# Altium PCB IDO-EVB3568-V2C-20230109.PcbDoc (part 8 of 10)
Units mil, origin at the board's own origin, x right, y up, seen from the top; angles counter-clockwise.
Board outline 5318 x 3544 mil, 2 copper layers (TOP, BOTTOM), stack 6.8 mil thick; 790 components, 626 nets, 2890 pads, 1922 vias.
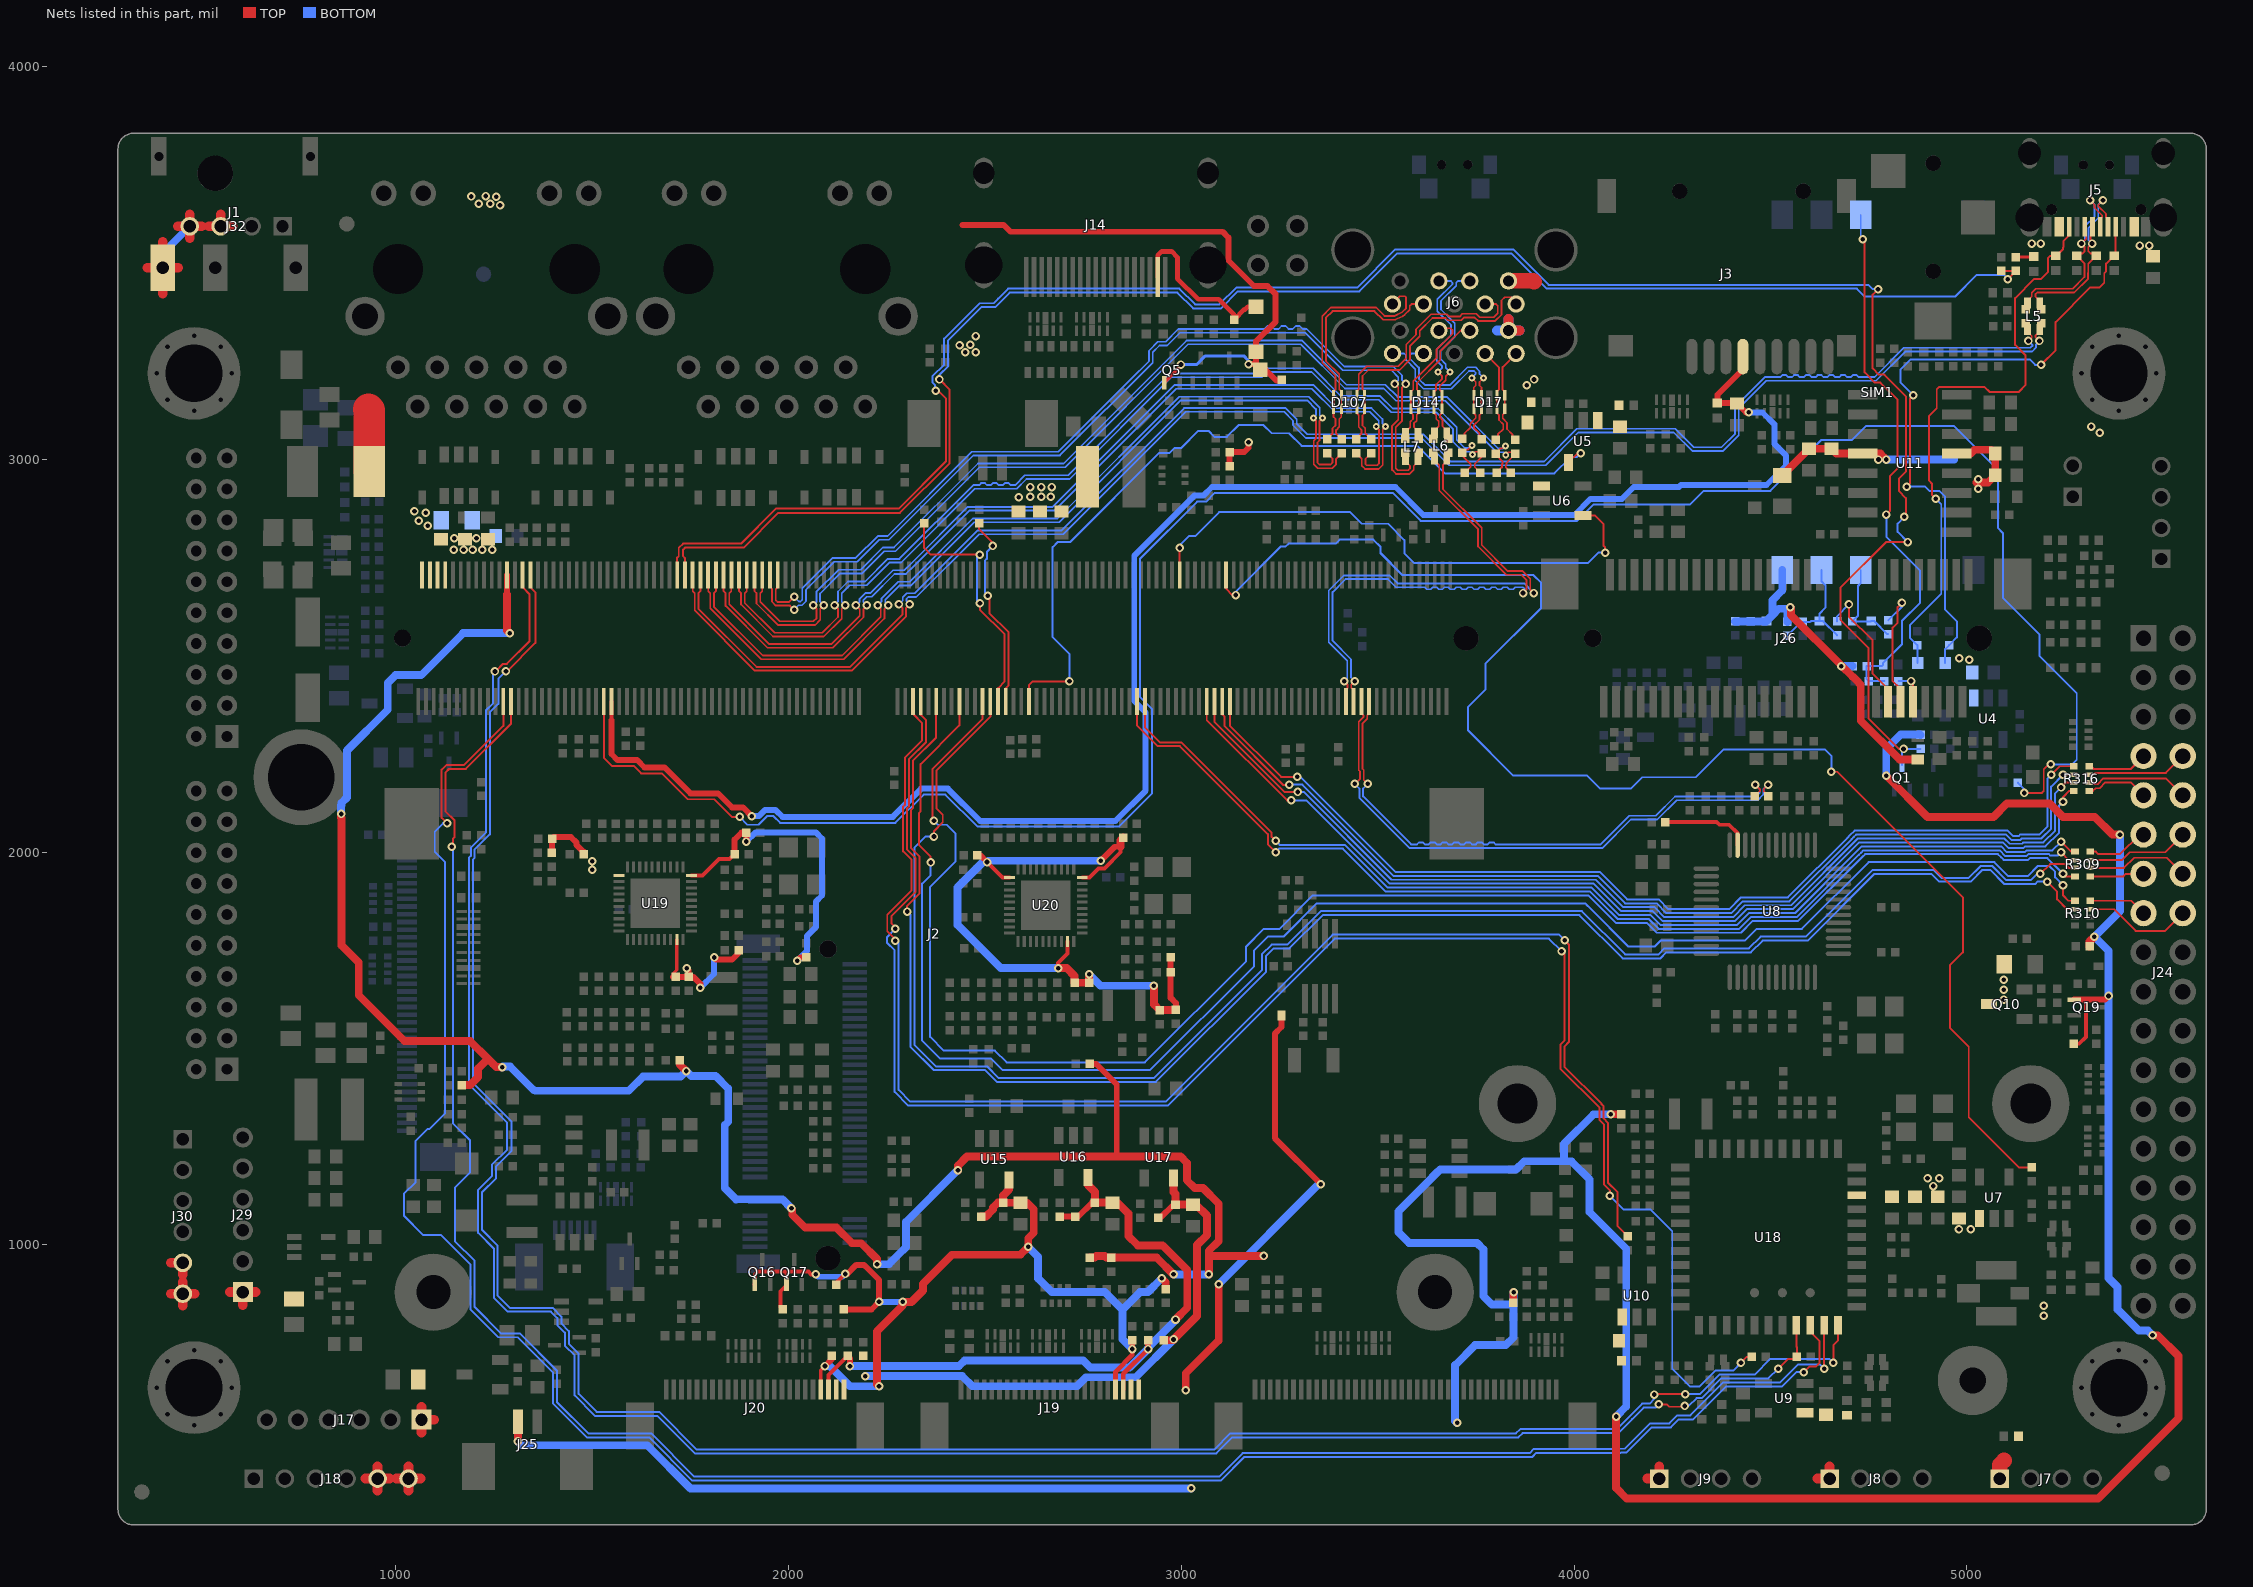
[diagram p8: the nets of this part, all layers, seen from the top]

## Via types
v1: diameter 21.65, hole 11.81, TOP to BOTTOM, 1878 vias
v2: diameter 17.72, hole 7.87, TOP to BOTTOM, 44 vias

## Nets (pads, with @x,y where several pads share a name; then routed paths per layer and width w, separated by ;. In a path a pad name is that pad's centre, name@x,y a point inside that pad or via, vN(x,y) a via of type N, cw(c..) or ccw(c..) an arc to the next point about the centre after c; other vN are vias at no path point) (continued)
TYPEC_CC1: D8.2 D11.C J5.A5 R38.1 | length 1694.8
  TOP w5: v1(4847,2931) 4855,2939 4855,3155 v1(4864,3164) ; v1(5189,3241) 5226,3278 5226,3350 5313.67,3437.67 5337.59,3437.67 5350,3450.08 5350,3474 5355,3479 5355,3498.9 D8.2@5375,3518.9 5379.21,3523.11 J5.A5@5379.21,3592.99
  BOTTOM w5: v1(4847,2931) 4894,2931 4905,2920 4930,2920 4945,2905 4945,2618 4975,2588 4975,2547.28 R38.1@4955,2527.28 4945,2517.28 D11.C@4945,2481.93 ; v1(4864,3164) 4831,3197 4831,3229 4857,3255 5160,3255 5174,3241 v1(5189,3241)
TYPEC_CC2: D9.2 D13.C J5.B5 R40.1 | length 1491.7
  TOP w5: v1(4920.5,2900.5) 4911,2910 4911,2939 4904,2946 4904,3111 4923.5,3130.5 4923.5,3178.5 4930,3185 5045,3185 5058,3172 5132,3172 5150,3190 5150,3265 5123,3292 5123,3411 5172,3460 5189.08,3460 5207,3477.92 5207,3513.9 5212,3518.9 D9.2@5227,3518.9 5227.98,3518.9 5245.22,3536.13 5245.22,3540.22 5246,3541 5246,3555.9 5261.1,3571 J5.B5@5261.1,3592.99
  BOTTOM w5: D13.C@4875,2481.93 4875,2526.28 R40.1@4874,2527.28 4855,2546.28 4855,2578 4935,2658 4935,2886 v1(4920.5,2900.5)
UART0_CTSN: J2.134 R310.2 | length 4346.6
  TOP w5: v1(2301.67,1849) 2301.67,1849.33 2301,1850 2301,1862.71 2333,1894.71 2333,1989.43 2311.67,2010.76 2311.67,2108.16 2316,2112.49 2316,2232.57 2375.59,2292.16 J2.134@2375.59,2383.58 ; v1(5205,1925) 5230,1900 5230,1880 5255.16,1854.84 R310.2@5275.31,1854.84
  BOTTOM w5: v1(2301.67,1849) 2302,1849 2310,1841 2310,1505 2370,1445 2500,1445 2530,1415 2935,1415 3215,1695 3215,1735 3235,1755 3275,1755 3360,1840 4013.57,1840 4123.57,1730 4220,1730 4235,1745 4450,1745 4480,1775 4595,1775 4765,1945 4910,1945 4930,1925 5010,1925 5040,1955 5060,1955 5096,1919 5174,1919 5180,1925 v1(5205,1925)
UART0_CTSN_: J24.16 R310.7 | length 276.7
  TOP w5: R310.7@5314.69,1854.84 5375.16,1854.84 5430,1800 5505,1800 J24.16@5550,1845
UART0_RTSN: J2.128 R310.1 | length 4313.6
  TOP w5: v1(2361.33,1974) 2361,1974.33 2361,1989.71 2331.67,2019.04 2331.67,2099.88 2336,2104.21 2336,2224.28 2434.64,2322.93 J2.128@2434.64,2383.58 ; v1(5245,1916) 5245,1890 5258.5,1876.5 R310.1@5275.31,1876.5
  BOTTOM w5: v1(2361.33,1974) 2361.33,1941.61 2340,1920.29 2340,1520 2385,1475 2515,1475 2545,1445 2920,1445 3185,1710 3185,1750 3220,1785 3260,1785 3345,1870 4028.29,1870 4034.14,1864.14 4040,1858.29 4138.29,1760 4205,1760 4220,1775 4435,1775 4465,1805 4580,1805 4750,1975 5070,1975 5106,1939 5155,1939 5181,1965 5210,1965 5225,1950 5225,1936 v1(5245,1916)
UART0_RTSN_: J24.15 R310.8 | length 148.4
  TOP w5: R310.8@5314.69,1876.5 5418.5,1876.5 J24.15@5450,1845
UART0_RX: J2.120 R309.3 | length 4361.4
  TOP w5: v1(2370,2040) 2370,2054 2392.33,2076.33 2392.33,2095.59 2376,2111.92 2376,2207.71 2513.38,2345.09 J2.120@2513.38,2383.58 ; v1(5187,1945) 5212,1970 5250,1970 5259.84,1960.16 R309.3@5275.31,1960.16
  BOTTOM w5: v1(2370,2040) 2348,2040 2320,2012 2320,1510 2375,1455 2505,1455 2535,1425 2930,1425 3205,1700 3205,1740 3230,1765 3270,1765 3355,1850 4020,1850 4130,1740 4215,1740 4230,1755 4445,1755 4475,1785 4590,1785 4760,1955 4915,1955 4935,1935 5005,1935 5035,1965 5065,1965 5101,1929 5163,1929 5179,1945 v1(5187,1945)
UART0_RX_: J24.14 R309.6 | length 263
  TOP w5: R309.6@5314.69,1960.16 5400.16,1960.16 5426,1986 5509,1986 J24.14@5550,1945
UART0_TX: J2.122 R309.4 | length 4260.1
  TOP w5: v1(2370,2080) 2366,2084 2366,2211.86 2493.7,2339.56 J2.122@2493.7,2383.58 ; v1(5245,1945) 5251.5,1938.5 R309.4@5275.31,1938.5
  BOTTOM w5: v1(2370,2080) 2380,2070 2402,2070 2425,2047 2425,1977 2360,1912 2360,1530 2395,1495 2525,1495 2555,1465 2907,1465 3165,1723 3165,1760 3210,1805 3250,1805 3335,1890 4036.58,1890 4054.14,1872.43 4060,1866.57 4106.57,1820 4185,1820 4210,1795 4425,1795 4455,1825 4570.86,1825 4735,1989.14 4740.85,1995 5079.22,1995 5087.51,1986.71 5093.89,1980.33 5156.1,1980.33 5160.78,1985 5205,1985 v1(5245,1945)
UART0_TX_: J24.13 R309.5 | length 138
  TOP w5: R309.5@5314.69,1938.5 5398.5,1938.5 5405,1945 J24.13@5450,1945
UART2_RX_M0: J2.116 R25.1 | length 504.3
  TOP w5: R25.1@2485,2837.28 2485,2823 2520,2788 v1(2520,2780) ; v1(2507,2653) 2511,2649 2511,2609 2560,2560 2560,2425 2552.75,2417.75 J2.116@2552.75,2383.58
  BOTTOM w5: v1(2507,2653) 2507,2654 2500,2661 2500,2743 2505,2748 2505,2765 v1(2520,2780)
UART2_TX_M0: J2.118 R26.1 | length 623.9
  TOP w5: R26.1@2345,2837.28 2345,2775 2362,2758 v1(2486.5,2758) ; v1(2487,2634) 2487,2618 2550,2555 2550,2435 2533.07,2418.07 J2.118@2533.07,2383.58
  BOTTOM w5: v1(2486.5,2758) 2480,2751.5 2480,2641 v1(2487,2634)
UART4_RX: J24.12 R309.7 | length 262.3
  TOP w5: R309.7@5314.69,1979.84 5339.84,1979.84 5340,1980 5395,1980 5415,2000 5505,2000 J24.12@5550,2045
UART4_RX_M1: J2.82 R309.2 | length 2789.7
  TOP w5: J2.82@2887.4,2383.58 2887.4,2322.6 2940,2270 2996,2270 3220,2046 3220,2020 v1(3240,2000) ; v1(5240,2000) 5260.16,1979.84 R309.2@5275.31,1979.84
  BOTTOM w5: v1(3240,2000) 3249,2009 3411,2009 3520,1900 4040.72,1900 4064.14,1876.57 4070,1870.72 4110.72,1830 4190,1830 4215,1805 4301.43,1805 4420,1805 4450,1835 4566.71,1835 4725,1993.29 4730.85,1999.14 4736.71,2005 5083.36,2005 5098.04,1990.33 5151.96,1990.33 5156.64,1995 5209.14,1995 5212.14,1992 5232,1992 v1(5240,2000)
UART4_TX: J24.11 R309.8 | length 158.7
  TOP w5: R309.8@5314.69,2001.5 5328.51,2001.5 5335,1995 5390,1995 5440,2045 J24.11@5450,2045
UART4_TX_M1: J2.80 R309.1 | length 2759.3
  TOP w5: J2.80@2907.08,2383.58 2907.08,2317.92 2945,2280 3000.14,2280 3230,2050.14 3230,2039 v1(3240,2029) ; v1(5240,2027) 5265.5,2001.5 R309.1@5275.31,2001.5
  BOTTOM w5: v1(3240,2029) 3250,2019 3416,2019 3525,1910 4045,1910 4115,1840 4195,1840 4220,1815 4305.57,1815 4415,1815 4445,1845 4562.57,1845 4715,1997.43 4720.85,2003.29 4732.57,2015 5079.22,2015 5087.51,2015 5102.18,2000.33 5147.82,2000.33 5152.49,2005 5218,2005 v1(5240,2027)
UART5_RX: J24.10 R316.6 | length 263.8
  TOP w5: R316.6@5311.69,2177.67 5322.33,2177.67 5326.46,2173.54 5333.54,2173.54 5348,2188 5507,2188 J24.10@5550,2145
UART5_RX_M1: J2.62 R316.3 | length 2654.3
  TOP w5: J2.62@3084.25,2383.58 3084.25,2331.75 3262.5,2153.5 v1(3296,2153.5) ; v1(5240,2165) 5252.67,2177.67 R316.3@5272.31,2177.67
  BOTTOM w5: v1(3296,2153.5) 3311.5,2153.5 3535,1930 4055,1930 4125,1860 4205,1860 4230,1835 4313.86,1835 4405,1835 4435,1865 4552.43,1865 4716.57,2029.14 4722.43,2035 5070.94,2035 5095.79,2035 5109.12,2021.67 5140.88,2021.67 5144.21,2025 5195,2025 5225,2055 5225,2150 v1(5240,2165)
UART5_TX: J24.9 R316.5 | length 161.1
  TOP w5: R316.5@5311.69,2156.02 5321.02,2156.02 5328,2163 5338,2163 5353,2178 5417,2178 J24.9@5450,2145
UART5_TX_M1: J2.64 R316.4 | length 2662.9
  TOP w5: J2.64@3064.56,2383.58 3064.56,2336.44 3269,2132 v1(3280,2132) ; v1(5245,2129) 5245,2140 5261.02,2156.02 R316.4@5272.31,2156.02
  BOTTOM w5: v1(3280,2132) 3318,2132 3530,1920 4050,1920 4120,1850 4200,1850 4225,1825 4309.71,1825 4410,1825 4440,1855 4556.57,1855 4726.57,2025 5075.08,2025 5091.65,2025 5106.32,2010.33 5143.68,2010.33 5148.35,2015 5200,2015 5235,2050 5235,2119 v1(5245,2129)
UART7_RX: J24.7 R316.8 | length 154.9
  TOP w5: R316.8@5311.69,2219.01 5315.99,2219.01 5323,2212 5417,2212 J24.7@5450,2245
UART7_RX_M1: J2.58 R316.1 | length 2636.8
  TOP w5: J2.58@3123.62,2383.58 3123.62,2322.38 3254,2192 v1(3295,2192) ; v1(5215,2197) 5237.01,2219.01 R316.1@5272.31,2219.01
  BOTTOM w5: v1(3295,2192) 3303,2192 3545,1950 4065,1950 4135,1880 4215,1880 4240,1855 4322.14,1855 4395,1855 4425,1885 4544.14,1885 4696.57,2037.43 4702.43,2043.29 4714.14,2055 5062.65,2055 5104.08,2055 5109.93,2049.15 5117.41,2041.67 5132.59,2041.67 5135.92,2045 5185,2045 5205,2065 5205,2187 v1(5215,2197)
UART7_TX: J24.8 R316.7 | length 258
  TOP w5: R316.7@5311.69,2197.36 5322.36,2197.36 5327,2202 5507,2202 J24.8@5550,2245
UART7_TX_M1: J2.60 R316.2 | length 2645.3
  TOP w5: J2.60@3103.93,2383.58 3103.93,2351.07 3110,2345 3110,2321 3260,2171 3274,2171 v1(3275,2172) ; v1(5245,2197.36) R316.2@5272.31,2197.36
  BOTTOM w5: v1(3275,2172) 3308,2172 3540,1940 4060,1940 4130,1870 4210,1870 4235,1845 4318,1845 4400,1845 4430,1875 4548.29,1875 4706.57,2033.29 4712.43,2039.14 4718.28,2045 5066.79,2045 5099.93,2045 5113.26,2031.67 5136.74,2031.67 5140.06,2035 5190,2035 5215,2060 5215,2167.36 v1(5245,2197.36)
UART8_CTSN_M0: J2.233 R201.1 U18.41 | length 5767.1
  TOP w5: v1(1252.07,2460.37) 1253.7,2462 1255,2462 1272.5,2479.5 1282.5,2479.5 1340,2537 1340,2657 1322.44,2674.56 J2.233@1322.44,2706.42 ; v1(4216,594) 4236,594 4242,588 4280,588 v1(4282,590) ; v1(4520,685) 4545,710 4562.28,710 R201.1@4567.28,715 4567.28,740 4565.87,741.41 U18.41@4565.87,795.59
  BOTTOM w5: v1(1252.07,2460.37) 1250.37,2460.37 1246.5,2456.5 1246.5,2378.5 1229,2361 1229,2049.72 1190.5,2011.21 1190.5,1990.5 1185.67,1985.67 1185.67,1408.63 1283,1311.31 1283,1243 1245,1205 1245,1176 1209,1140 1209,1031 1249,991 1249,866 1285,830 1394.57,830 1411,813.57 1411,795.92 1430.33,776.59 1430.33,760.39 ; 1430.32,760.39 1430.32,743.82 1455,719.14 1455,616.72 1506.71,565 1665,565 1761,469 3089,469 3130,510 3858,510 3869,521 4112.57,521 4147.96,556.39 4177.24,585.67 4177.56,585.99 4208,586 v1(4216,594) ; v1(4282,590) 4292,590 4312,610 4325,610 4375,660 4495,660 v1(4520,685)
UART8_RTSN_M0: J2.231 U18.44 | length 5856.7
  TOP w5: v1(1280,2461) 1283,2461 1355,2533 1355,2662 1342.12,2674.88 J2.231@1342.12,2706.42 ; v1(4204,619) 4205,620 v1(4283,620) ; v1(4660,700) 4660,745 4672.17,757.17 U18.44@4672.17,795.59
  BOTTOM w5: v1(1280,2461) 1280,2460.92 1260.67,2441.59 1260.67,2377.67 1239,2356 1239,2045.57 1200.5,2007.07 1200.5,1985.5 1195.67,1980.67 1195.67,1412.78 1294,1314.45 1294,1239 1255,1200 1255,1170 1219,1134 1219,1038.24 1259,998.24 1259,871 1290,840 1398.71,840 1421,817.71 1421,800.06 1440.33,780.74 1440.33,756.25 ; 1440.32,756.24 1440.32,747.96 1465,723.29 1465,620.86 1510.86,575 1670,575 1766,479 3084,479 3125,520 3851.86,520 3862.86,531 4108.43,531 4137.96,560.53 4173.1,595.67 4173.43,596 4192.08,596 4204,607.92 v1(4204,619) ; v1(4283,620) 4320,620 4370,670 4460,670 4500,710 4650,710 v1(4660,700)
UART8_RX_M0: J2.238 U18.42 | length 5709.7
  TOP w5: v1(1130,2074) 1116.46,2087.54 1116.46,2210.46 1128,2222 1172.71,2222 1173.21,2222.5 1173.76,2222.5 1273.22,2321.96 J2.238@1273.22,2383.58 ; v1(4585,676) 4599,690 4615,690 4625,700 4625,755 4601.3,778.7 U18.42@4601.3,795.59
  BOTTOM w5: v1(1130,2074) 1120.08,2074 1098.67,2052.59 1098.67,2001.33 1125,1975 1125,1929.14 1125,1335 1085,1295 1080,1295 1050,1265 1050,1160 1020,1130 1020,1075 1070,1025 1115,1025 1190,950 1190,835 1260,765 1310,765 1400,675 1400,595.86 1485.86,510 1645,510 1755,400 3100,400 3160,460 3893,460 3903.5,470.5 4118.64,470.5 4119.14,470.99 4133.28,470.99 4197.96,535.67 4246.67,535.67 4267,556 4303,556 4387,640 4530,640 4566,676 v1(4585,676)
UART8_TX_M0: J2.236 U18.43 | length 5599.3
  TOP w5: v1(1142,2014) 1145,2017 1145,2034.08 1149,2038.08 1149,2080.92 1126.46,2103.46 1126.46,2203.46 1135,2212 1176.86,2212 1177.35,2212.5 1177.9,2212.5 1292.91,2327.5 J2.236@1292.91,2383.58 ; v1(4636.73,685) U18.43@4636.73,795.59
  BOTTOM w5: v1(1142,2014) 1142,2009 1145,2006 1145,1977.57 1145,1310 1189,1266 1189,1185 1150,1146 1150,1010 1200,960 1200,842 1267,775 1315,775 1410,680 1410,600 1490,520 1650,520 1760,410 3095.86,410 3155.86,470 3887.14,470 3897.64,480.5 4114.5,480.5 4114.99,480.99 4129.14,480.99 4187.96,539.82 4193.81,545.67 4242.53,545.67 4262.86,566 4296,566 4380,650 4525,650 4570,695 4626.73,695 v1(4636.73,685)
USB1_PWREN_H_GPIO3_A5: J2.59 R57.1 | length 3764.6
  TOP w5: J2.59@3113.77,2706.42 3113.77,2671.23 3130,2655 v1(3138,2655) ; v1(4655,2205) 4670,2205 4990,1885 4990,1745 4957,1712 4957,1553 5005,1505 5005,1325 5132.28,1197.72 R57.1@5165,1197.72
  BOTTOM w5: v1(3138,2655) 3138,2663 3253.63,2778.63 3265.63,2778.63 3273,2786 3393,2786 3403,2796 3489,2796 3507,2778 3507,2762 3563,2706 3896,2706 3916,2686 3916,2622 3774,2480 3774,2414 3730,2370 3730,2310 3845,2195 4016.86,2195 4033.43,2195 4066.43,2162 4144,2162 4173,2191 4174.71,2191 4191.28,2191 4309.71,2191 4380.71,2262 4638,2262 4656,2244 4656,2206 v1(4655,2205)
USB2_HOST2_DM: J2.28 L6.2 R42.1 | length 1348
  TOP w4.5: v1(3414.82,2435.18) 3423.32,2426.68 3423.32,2418.32 3418.89,2413.89 J2.28@3418.89,2383.58 ; R42.1@3679,3017.28 3675.75,3014.03 L6.2@3675.75,3001.53 3675.75,2995.75 3666,2986 3666,2925 3765,2826 3765,2782.44 3831.44,2716 3869,2716 3888.5,2696.5 3888.5,2668.5 v1(3897,2660)
  BOTTOM w4.5: v1(3414.82,2435.18) 3422.5,2442.87 3422.5,2487.5 3375.5,2534.5 3375.5,2666.5 3414,2705 3530,2705 3550.5,2684.5 3873.57,2684.5 3883.64,2674.44 3883.64,2673.36 v1(3897,2660)
USB2_HOST2_DM_: D14.5 D14.6 J6.2 L6.3 R42.2 | length 512.4
  TOP w4.5: R42.2@3679,3052.72 3675.75,3055.97 L6.3@3675.75,3068.47 3675.75,3074.25 3664.6,3085.4 3664.6,3101.4 3658.68,3107.32 3658.68,3113.68 3663.37,3118.37 D14.5@3663.37,3128.78 D14.6@3663.37,3163.22 3663.37,3172.63 3658.2,3177.8 3658.2,3187.2 3673.28,3202.28 3673.28,3212.5 v2(3683.53,3222.75)
  BOTTOM w4.5: v2(3683.53,3222.75) 3673,3233.28 3673,3243.03 3660.03,3256 3660.03,3277.03 3696,3313 3696,3347 3661,3382 3661,3404 3699.75,3442.75 3699.75,3450.5 3704.25,3455 J6.2@3734.37,3455
USB2_HOST2_DP: J2.26 L6.1 R43.1 | length 1348.6
  TOP w4.5: J2.26@3438.58,2383.58 3438.58,2413.42 3432.82,2419.18 3432.82,2426.32 v1(3441.68,2435.18) ; R43.1@3641,3017.28 3644.25,3014.03 L6.1@3644.25,3001.53 3644.25,2997.75 3656.5,2985.5 3656.5,2921.06 3755.5,2822.06 3755.5,2778.5 3827.5,2706.5 3865.06,2706.5 3879,2692.56 3879,2669 v1(3870,2660)
  BOTTOM w4.5: v1(3441.68,2435.18) 3432,2444.87 3432,2491.44 3385,2538.44 3385,2662.57 3417.93,2695.5 3526.06,2695.5 3546.56,2675 3620,2675 3625,2670 3635,2670 3640,2675 3650,2675 3655,2670 3665,2670 3670,2675 3680,2675 3685,2670 3695,2670 3700,2675 3710,2675 3715,2670 3725,2670 3730,2675 3740,2675 3745,2670 3755,2670 3760,2675 3770,2675 3775,2670 3785,2670 3790,2675 3800,2675 3805,2670 3815,2670 3820,2675 3830,2675 3835,2670 3845,2670 3850,2675 3869.64,2675 3874.14,2670.5 3874.14,2664.14 v1(3870,2660)
USB2_HOST2_DP_: D14.4 D14.7 J6.3 L6.4 R43.2 | length 512.4
  TOP w4.5: R43.2@3641,3052.72 3644.25,3055.97 L6.4@3644.25,3068.47 3644.25,3074.25 3655.1,3085.1 3655.1,3097.46 3649.18,3103.38 3649.18,3112.82 3643.68,3118.32 D14.4@3643.68,3128.78 D14.7@3643.68,3163.22 3643.68,3172.68 3648.7,3177.69 3648.7,3191.13 3663.78,3206.21 3663.78,3212.5 v2(3653.52,3222.75)
  BOTTOM w4.5: v2(3653.52,3222.75) 3663.5,3232.73 3663.5,3239.1 3650.53,3252.06 3650.53,3280.97 3686.5,3316.94 3686.5,3343.06 3651.5,3378.06 3651.5,3407.94 3690.25,3446.69 3690.25,3450.5 3685.75,3455 J6.3@3655.63,3455
USB2_HOST2_PWREN_H_GPIO0_A6: J2.110 U5.4 | length 2107.9
  TOP w5: J2.110@2611.81,2383.58 2611.81,2425 2621.81,2435 v1(2715,2435) ; U5.4@3985.6,2992.85 4008.75,3016 v1(4017,3016)
  BOTTOM w5: v1(2715,2435) 2715,2505 2672,2548 2672,2777 2685,2790 2717,2790 2944,3017 2970,3017 2982,3029 2999,3029 3043,3073 3069,3073 3084,3058 3116,3058 3146,3088 3209,3088 3230,3067 3274,3067 3306,3035 3601,3035 3671,2965 3950,2965 3991,3006 4007,3006 v1(4017,3016)
USB2_HOST3_DM: J2.24 R71.2 | length 1471.7
  TOP w4.5: v1(3441.58,2174) 3455,2187.42 3455,2205.57 3451.42,2209.14 3451.42,2332 3463.43,2344.01 3463.43,2348.57 3458.26,2353.74 J2.24@3458.26,2383.58 ; v1(4493.93,2172.18) 4482.75,2161 4482.75,2154.97 R71.2@4495,2142.72
  BOTTOM w4.5: v1(3441.58,2174) 3453.26,2162.32 3453.26,2138.3 3581.06,2010.5 4071.5,2010.5 4144.5,2083.5 4211.94,2083.5 4260.94,2132.5 4467.37,2132.5 4482,2147.13 4482,2160.25 v1(4493.93,2172.18)
USB2_HOST3_DP: J2.22 R69.2 | length 1468.3
  TOP w4.5: v1(3474.44,2174) 3464.5,2183.94 3464.5,2209.5 3460.92,2213.08 3460.92,2324.49 3461,2324.57 3461,2327 3473.5,2339.5 3473.5,2348.5 3477.95,2352.95 J2.22@3477.95,2383.58 ; R69.2@4460,2142.72 4473.25,2155.97 4473.25,2160 v1(4461.07,2172.18)
  BOTTOM w4.5: v1(3474.44,2174) 3462.76,2162.32 3462.76,2142.24 3585,2020 3600,2020 3605,2025 3615,2025 3620,2020 3630,2020 3635,2025 3645,2025 3650,2020 3660,2020 3665,2025 3675,2025 3680,2020 3690,2020 3695,2025 3705,2025 3710,2020 3720,2020 3725,2025 3735,2025 3740,2020 3750,2020 3755,2025 3765,2025 3770,2020 3780,2020 3785,2025 3795,2025 3800,2020 4067.56,2020 4140.56,2093 4208,2093 4257,2142 4463.44,2142 4472.5,2151.06 4472.5,2160.75 v1(4461.07,2172.18)
USB2_PWREN_H_GPIO4_C3: J2.138 R70.1 | length 4456.7
  TOP w5: v1(2271.67,1805) 2271.67,1808.33 2262,1818 2262,1837.86 2323,1898.86 2323,1985.29 2301.67,2006.61 2301.67,2112.31 2306,2116.64 2306,2236.71 2350,2280.71 2350,2336 2336.22,2349.78 J2.138@2336.22,2383.58 ; v1(3968,1748) 3975,1741 3975,1520 3965,1510 3965,1449 4065,1349 4065,1318 4076,1307 4076,1154 4091,1139 v1(4091,1125) ; v1(4425,700) 4440,715 R70.1@4452.28,715
  BOTTOM w5: v1(2271.67,1805) 2250.34,1783.66 2250.34,1769.66 2270,1750 2270,1390 2305,1355 2965,1355 3390,1780 3936,1780 v1(3968,1748) ; v1(4091,1125) 4126,1090 4195,1090 4250,1035 4250,685 4295,640 4320,640 4360,680 4405,680 v1(4425,700)
USB3_HOST1_DM: J2.169 L7.2 R46.1 | length 2408.6
  TOP w4.5: J2.169@1952.36,2706.42 1952.36,2675.64 1957.45,2670.55 1957.45,2638.06 1967.51,2628 2003,2628 2013.68,2617.32 v1(2013.77,2617.32) ; v1(3543.32,3192.45) 3552,3183.77 3552,3101.44 3536.5,3085.94 3536.5,2973.56 3546.56,2963.5 3581.57,2963.5 3591.64,2973.56 3591.64,2983.63 3602.75,2994.75 L7.2@3602.75,2999.53 3602.75,3016.03 R46.1@3604,3017.28
  BOTTOM w4.5: v1(2013.77,2617.32) 2013.77,2617.77 2025,2629 2033.94,2629 2044,2639.06 2044,2668 2116,2740 2175,2740 2230.5,2795.5 2255.5,2795.5 2470.5,3010.5 2690.73,3010.5 2927,3246.77 2927,3273.29 2944.21,3290.5 2963.94,3290.5 2996.44,3323 3315.56,3323 3411.06,3227.5 3535.06,3227.5 3552.5,3210.06 3552.5,3201.64 v1(3543.32,3192.45)
USB3_HOST1_DM_: D14.2 D14.9 J6.11 L7.3 R46.2 | length 342.6
  TOP w4.5: L7.3@3602.75,3066.47 3602.75,3072.25 3592,3083 3592,3092 3599.22,3099.22 3599.22,3114.22 3604.32,3119.32 D14.2@3604.32,3128.78 D14.9@3604.32,3163.22 3604.32,3173.68 3600,3178 3600,3195 3659,3254 3659,3276 3712.02,3329.02 J6.11@3734.37,3329.02
USB3_HOST1_DP: J2.167 L7.1 R47.1 | length 2396.6
  TOP w4.5: J2.167@1972.04,2706.42 1972.04,2675.04 1966.95,2669.95 1966.95,2642 1971.45,2637.5 2001.09,2637.5 v1(2013.77,2650.18) ; R47.1@3570,3017.28 3571.25,3016.03 L7.1@3571.25,2999.53 3571.25,2994.75 3582.14,2983.86 3582.14,2977.5 3577.64,2973 3550.5,2973 3546,2977.5 3546,3082 3561.5,3097.5 3561.5,3182.77 v1(3571.18,3192.45)
  BOTTOM w4.5: v1(2013.77,2650.18) 2025.45,2638.5 2030,2638.5 2034.5,2643 2034.5,2671.94 2112.06,2749.5 2171.06,2749.5 2226.56,2805 2251.56,2805 2466.56,3020 2686.79,3020 2869.98,3203.19 ; 2870.04,3203.25 2917.5,3250.71 2917.5,3277.23 2940.27,3300 2960,3300 2992.5,3332.5 3211.5,3332.5 3219,3340 3229.5,3340 3237,3332.5 3247.5,3332.5 3255,3340 3265.5,3340 3273,3332.5 3283.5,3332.5 3291,3340 3301.5,3340 3309,3332.5 3319.5,3332.5 3415,3237 3539,3237 3562,3214 3562,3201.64 v1(3571.18,3192.45)
USB3_HOST1_DP_: D14.1 D14.10 J6.12 L7.4 R47.2 | length 355.4
  TOP w4.5: L7.4@3571.25,3066.47 3571.25,3071.25 3582.5,3082.5 3582.5,3095.94 3589.72,3103.16 3589.72,3114.28 3584.63,3119.37 D14.1@3584.63,3128.78 D14.10@3584.63,3163.22 3584.63,3172.63 3590.5,3178.5 3590.5,3198.94 3649.5,3257.94 3649.5,3279.94 3690.25,3320.69 3690.25,3329.75 3685.75,3334.25 3660.86,3334.25 J6.12@3655.63,3329.02
USB3_HOST1_PWREN_H_GPIO3_A0: J2.71 U6.4 | length 1413.4
  TOP w5: J2.71@2995.66,2706.42 2995.66,2774.3 v1(2996.14,2774.77) ; U6.4@4023.15,2857.6 4052.4,2857.6 4075,2835 4075,2780 4079,2776 v1(4079,2763)
  BOTTOM w5: v1(2996.14,2774.77) 2996.14,2774.86 2996.04,2774.96 2996.04,2782.04 3019,2805 3035,2805 3096,2866 3430,2866 3459.5,2836.5 3526.5,2836.5 3568,2795 3568,2761 3593,2736 4035,2736 4062,2763 v1(4079,2763)
USB3_HOST1_SSRXN: J2.175 R375.1 R423.1 | length 2498
  TOP w4.5: J2.175@1893.3,2706.42 1893.3,2665.04 1888.21,2659.95 1888.21,2634.79 1964,2559 2085.56,2559 2125.5,2598.93 2125.5,2620.59 v1(2116.82,2629.27) ; R423.1@3722,2966.72 3736.96,2981.68 3736.96,2988.04 3715,3010 R375.1@3715,3017.28 3722.72,3025 3729,3025 v2(3740,3036)
  BOTTOM w4.5: v1(2116.82,2629.27) 2125.5,2637.95 2125.5,2663.93 2151.06,2689.5 2195.06,2689.5 2252.56,2747 2282,2747 2470,2935 2485,2935 2490,2940 2500,2940 2505,2935 2515,2935 2520,2940 2530,2940 2535,2935 2545,2935 2550,2940 2560,2940 2565,2935 2576.56,2935 2601.56,2960 2711.58,2960 2970.58,3219 3200.5,3219 3214,3232.5 3335.5,3232.5 3406.5,3161.5 3506.5,3161.5 3538,3130 3653.44,3130 3701,3082.44 3701,3050 3721.5,3029.5 3733.5,3029.5 v2(3740,3036)
USB3_HOST1_SSRXN_: D17.1 D17.10 J6.14 R375.2 | length 489.6
  TOP w4.5: R375.2@3715,3052.72 3721,3058.72 3721,3067 3735.4,3081.4 3735.4,3091.4 3749.72,3105.72 3749.72,3113.28 3744.63,3118.37 D17.1@3744.63,3128.78 D17.10@3744.63,3163.22 3744.63,3183.54 3749.72,3188.63 3749.72,3197.5 v2(3739.47,3207.75)
  BOTTOM w4.5: J6.14@3537.52,3269.96 3567.64,3269.96 3572.14,3265.46 3572.14,3253.42 3595.28,3230.28 3595.28,3201.28 3616.56,3180 3687,3180 3732.5,3225.5 3745.22,3225.5 3749.72,3221 3749.72,3218.01 v2(3739.47,3207.75)
USB3_HOST1_SSRXP: J2.177 R376.1 R422.1 | length 2495.4
  TOP w4.5: J2.177@1873.62,2706.42 1873.62,2665.04 1878.71,2659.95 1878.71,2630.85 1960.06,2549.5 2089.5,2549.5 2135,2595 2135,2620.59 v1(2143.68,2629.27) ; v2(3741,3013) 3748,3020 3761.28,3020 R376.1@3765,3016.28 3765,3007 3746.75,2988.75 3746.75,2980.97 R422.1@3761,2966.72
  BOTTOM w4.5: v1(2143.68,2629.27) 2135,2637.95 2135,2660 2155,2680 2199,2680 2256.5,2737.5 2285.94,2737.5 2473.94,2925.5 2580.5,2925.5 2605.5,2950.5 2715.51,2950.5 2974.51,3209.5 3204.43,3209.5 3217.93,3223 3331.56,3223 3402.56,3152 3502.56,3152 3534.06,3120.5 3649.5,3120.5 3691.5,3078.5 3691.5,3046.06 3717.56,3020 3734,3020 v2(3741,3013)
USB3_HOST1_SSRXP_: D17.2 D17.9 J6.15 R376.2 | length 490.5
  TOP w4.5: R376.2@3765,3051.72 3759,3057.72 3759,3067 3744.9,3081.1 3744.9,3087.46 3759.22,3101.79 3759.22,3113.22 3764.32,3118.32 D17.2@3764.32,3128.78 D17.9@3764.32,3163.22 3764.32,3183.54 3759.22,3188.63 3759.22,3197.5 v2(3769.48,3207.75)
  BOTTOM w4.5: J6.15@3616.26,3269.96 3586.14,3269.96 3581.64,3265.46 3581.64,3257.36 3604.78,3234.22 3604.78,3205.22 3620.5,3189.5 3683.06,3189.5 3728.56,3235 3749.16,3235 3759.22,3224.94 3759.22,3218.01 v2(3769.48,3207.75)
USB3_HOST1_SSTXN: C187.1 C290.1 J2.171 | length 2544.5
  TOP w4.5: J2.171@1932.67,2706.42 1932.67,2665.04 1927.58,2659.95 1927.58,2637.42 1977,2588 2063,2588 2071,2596 2071,2620.32 v1(2062.32,2629) ; C187.1@3803,2966.72 3816.25,2979.97 3816.25,2988.25 3818.5,2990.5 3818.5,2994.36 3800,3012.86 C290.1@3800,3015.28 3813.72,3029 3818,3029 3824,3035 v2(3825,3035)
  BOTTOM w4.5: v1(2062.32,2629) 2070.5,2637.18 2070.5,2662.94 2127.06,2719.5 2183.06,2719.5 2239.56,2776 2268,2776 2482,2990 2700,2990 3013,3303 3307.99,3303 3420.49,3190.5 3519.5,3190.5 3550.5,3159.5 3675.94,3159.5 3807.44,3028 3818,3028 v2(3825,3035)
USB3_HOST1_SSTXN_: C290.2 D17.4 D17.7 J6.17 | length 250.3
  TOP w4.5: J6.17@3773.74,3269.96 3808.5,3235.2 3808.5,3177.5 3803.68,3172.68 D17.7@3803.68,3163.22 D17.4@3803.68,3128.78 3803.68,3118.32 3808.78,3113.22 3808.78,3100.79 3819.6,3089.96 3819.6,3077.6 3806,3064 3806,3056.72 C290.2@3800,3050.72
USB3_HOST1_SSTXP: C189.1 C291.1 J2.173 | length 2557.8
  TOP w4.5: J2.173@1912.99,2706.42 1912.99,2665.04 1918.08,2659.95 1918.08,2633.48 1973.06,2578.5 2066.94,2578.5 2080.5,2592.06 2080.5,2620.32 v1(2089.18,2629) ; v2(3826,3012) 3832.52,3018.52 3846.76,3018.52 C291.1@3850,3015.28 3850,3014 3828,2992 3828,2986.56 3825.75,2984.31 3825.75,2979.97 C189.1@3839,2966.72
  BOTTOM w4.5: v1(2089.18,2629) 2080,2638.18 2080,2659 2131,2710 2187,2710 2243.5,2766.5 2271.94,2766.5 2485.94,2980.5 2703.94,2980.5 3016.94,3293.5 3304.05,3293.5 3416.55,3181 3515.56,3181 3546.56,3150 3672,3150 3803.5,3018.5 3819.47,3018.5 v2@3821.97,3016 ; v2@3822,3016 v2(3826,3012)
USB3_HOST1_SSTXP_: C291.2 D17.5 D17.6 J6.18 | length 251
  TOP w4.5: C291.2@3850,3050.72 3843,3057.72 3843,3064 3829.1,3077.9 3829.1,3093.9 3818.28,3104.72 3818.28,3114.28 3823.37,3119.37 D17.5@3823.37,3128.78 D17.6@3823.37,3163.22 3823.37,3172.63 3818,3178 3818,3235.48 J6.18@3852.48,3269.96
USB3_OTG0_DM: J2.189 L5.2 R29.1 | length 4219.3
  TOP w4.5: J2.189@1755.51,2706.42 1755.51,2665.04 1760.6,2659.95 1760.6,2615.96 1914.06,2462.5 2160.94,2462.5 2299,2600.56 2299,2622.65 v1(2307.68,2631.34) ; v1(5185,3302) 5174.82,3312.18 5174.82,3314.82 5185.75,3325.75 L5.2@5185.75,3331.53 5190,3335.79 R29.1@5190,3347.28
  BOTTOM w4.5: v1(2307.68,2631.34) 2299.94,2639.08 2299.94,2645.44 2304.5,2650 2325,2650 2485,2810 2699.29,2810 3010.79,3121.5 3261.5,3121.5 3284.22,3098.78 3284.22,3087.35 3316.56,3055 3612,3055 3681.5,2985.5 3927.5,2985.5 4011,3069 4254,3069 4301,3022 4379.44,3022 4419.5,3062.06 4419.5,3130.5 4489.5,3200.5 4768.94,3200.5 4843.44,3275 5166,3275 5176.5,3285.5 5176.5,3293.5 v1(5185,3302)
USB3_OTG0_DM_: D12.2 J5.A7 J5.B7 L5.3 R29.2 | length 569
  TOP w4.5: R29.2@5190,3382.72 5185.75,3386.97 L5.3@5185.75,3398.47 5185.75,3404.25 5174.75,3415.25 5174.75,3421 5179.25,3425.5 5273.57,3425.5 5308.95,3460.89 5308.95,3475.03 5309.5,3475.57 5309.5,3498.4 D12.2@5330,3518.9 5323.9,3525 5315,3525 5309.5,3530.5 5309.5,3540.5 v1(5319,3550) 5315,3554 5315,3569 5320.16,3574.16 J5.A7@5320.16,3592.99 ; v1(5346.68,3660.18) 5334.65,3648.15 5334.65,3645.35 5354.5,3625.5 5354.5,3617.5 5359.53,3612.47 J5.B7@5359.53,3592.99
  BOTTOM w4.5: v1(5319,3550) 5310.25,3558.75 5310.25,3590.25 5335,3615 5335,3648.5 v1(5346.68,3660.18)
USB3_OTG0_DP: J2.187 L5.1 R34.1 | length 4217.5
  TOP w4.5: J2.187@1775.19,2706.42 1775.19,2665.04 1770.1,2659.95 1770.1,2619.9 1918,2472 2157,2472 2289.5,2604.5 2289.5,2622.65 v1(2280.82,2631.34) ; R34.1@5150,3347.28 5150,3335.79 L5.1@5154.25,3331.53 5154.25,3325.75 5165.32,3314.68 5165.32,3310.32 v1(5157,3302)
  BOTTOM w4.5: v1(2280.82,2631.34) 2290.44,2640.96 2290.44,2649.38 2300.56,2659.5 2321.06,2659.5 2481.06,2819.5 2695.36,2819.5 3006.86,3131 3265.44,3131 3293.72,3102.72 3293.72,3091.28 3320.5,3064.5 3615.94,3064.5 3685.44,2995 3923.56,2995 4007.06,3078.5 4257.94,3078.5 4304.94,3031.5 4375.5,3031.5 4410,3066 4410,3134.44 4485.56,3210 4525,3210 4530,3215 4540,3215 4545,3210 4555,3210 4560,3215 4570,3215 4575,3210 4585,3210 4590,3215 4600,3215 4605,3210 4615,3210 4620,3215 4630,3215 4635,3210 4645,3210 4650,3215 4660,3215 4665,3210 4675,3210 4680,3215 4690,3215 4695,3210 4705,3210 4710,3215 4720,3215 4725,3210 4765,3210 4839.5,3284.5 5162.06,3284.5 5167,3289.44 5167,3292 v1(5157,3302)
USB3_OTG0_DP_: D10.2 J5.A6 J5.B6 L5.4 R34.2 | length 570.3
  TOP w4.5: R34.2@5150,3382.72 5154.25,3386.97 L5.4@5154.25,3398.47 5154.25,3404.25 5165.25,3415.25 5165.25,3424.94 5175.31,3435 5269.63,3435 5299.45,3464.82 5299.45,3478.97 5300,3479.51 5300,3498.9 D10.2@5280,3518.9 5286.1,3525 5295,3525 5300,3530 5300,3542 v1(5292,3550) 5304,3562 5304,3568 5300.47,3571.53 J5.B6@5300.47,3592.99 ; v1(5313.82,3660.18) 5325.15,3648.85 5325.15,3641.41 5345,3621.56 5345,3618 5339.84,3612.84 J5.A6@5339.84,3592.99
  BOTTOM w4.5: v1(5292,3550) 5300.75,3558.75 5300.75,3594.19 5325.5,3618.94 5325.5,3648.5 v1(5313.82,3660.18)
USB3_OTG0_ID: J2.193 Q1.3 R31.2 | length 5249.6
  TOP w5: J2.193@1716.14,2706.42 1716.14,2750.14 1720,2754 1720,2775 1731,2786 1878.54,2786 1967.54,2875 2280,2875 2400,2995 2400,3156 2385,3171 2379,3171 v1(2374.54,3175.46) ; v1(4774,3434) 4760,3420 4760,3232 4776,3216 4790,3216 4845,3161 4845,2969 4827,2951 4827,2920 4845,2902 4845,2858 v1(4841,2854) ; v1(4839,2263) 4827,2263 4750,2340 4750,2520 4678,2592 4678,2673 4795,2790 v1(4850,2790)
  BOTTOM w5: v1(2374.54,3175.46) 2373,3177 2373,3189.08 2365.67,3196.41 2365.67,3211.59 2396,3241.92 2396,3307.71 2486.29,3398 2521.72,3398 2533.43,3409.71 2558.72,3435 2612,3435 2995,3435 3035,3395 3096.86,3395 3139.86,3438 3448,3438 3545,3535 3845,3535 3935,3445 4749,3445 4760,3434 v1(4774,3434) ; Q1.3@4835,2221.5 4835,2259 v1(4839,2263) R31.2@4882.28,2263 ; v1(4841,2854) 4824,2837 4824,2816 v1(4850,2790)
USB3_OTG0_SSRXN: J2.183 R48.1 | length 2214.6
  TOP w4.5: J2.183@1814.56,2706.42 1814.56,2665.04 1809.47,2659.95 1809.47,2625.53 1934,2501 2136,2501 2234.5,2599.5 2234.5,2621.59 v1(2226.82,2629.27) ; v2(3359,3106) 3352,3099 3352,3049 3346.5,3043.5 3346.5,2992 3351,2987.5 3380,2987.5 3384.5,2992 3384.5,3002.78 R48.1@3371,3016.28
  BOTTOM w4.5: v1(2226.82,2629.27) 2236.66,2639.11 2236.66,2647.1 2278.56,2689 2308,2689 2469,2850 2684.57,2850 2994.56,3160 3324.44,3160 3352.07,3132.37 3352.07,3112.93 v2(3359,3106)
USB3_OTG0_SSRXN_: D107.1 D107.10 J6.5 R48.2 | length 651.8
  TOP w4.5: R48.2@3371,3051.72 3384.54,3065.26 3384.54,3078.98 3392.72,3087.16 3392.72,3103.37 3387.63,3108.46 D107.1@3387.63,3128.78 D107.10@3387.63,3163.22 3387.63,3173.41 3392.72,3178.5 3392.72,3212.84 3358.5,3247.06 3358.5,3364.94 3381.06,3387.5 3495.5,3387.5 3517.5,3365.5 3542.23,3365.5 3545,3367 3559.3,3373.53 3561.88,3375.32 3572.14,3385.58 3572.14,3412.86 3568.96,3416.04 3556.04,3416.04 3537.52,3397.52 J6.5@3537.52,3395.94
USB3_OTG0_SSRXP: J2.185 R49.1 | length 2245.8
  TOP w4.5: J2.185@1794.88,2706.42 1794.88,2665.04 1799.97,2659.95 1799.97,2621.59 1930.06,2491.5 2139.94,2491.5 2244,2595.56 2244,2619.59 v1(2253.68,2629.27) ; v2(3335.99,3106) 3342.5,3099.49 3342.5,3052.94 3337,3047.44 3337,2988.06 3347.06,2978 3383.94,2978 3394,2988.06 3394,3002.28 R49.1@3408,3016.28
  BOTTOM w4.5: v1(2253.68,2629.27) 2246.16,2636.8 2246.16,2643.16 2282.5,2679.5 2311.94,2679.5 2472.94,2840.5 2688.51,2840.5 2998.5,3150.5 3320.5,3150.5 3342.57,3128.43 3342.57,3112.57 v2(3335.99,3106)
USB3_OTG0_SSRXP_: D107.2 D107.9 J6.6 R49.2 | length 621.5
  TOP w4.5: R49.2@3408,3051.72 3394.04,3065.68 3394.04,3075.04 3402.22,3083.22 3402.22,3103.37 3407.32,3108.46 D107.2@3407.32,3128.78 D107.9@3407.32,3163.22 3407.32,3173.68 3402.22,3178.78 3402.22,3216.78 3368,3251 3368,3361 3385,3378 3491.56,3378 3513.56,3356 3544.64,3356 3549.24,3358.49 3564.02,3365.24 3568,3368 3581.64,3381.64 3581.64,3391.44 3586.14,3395.94 J6.6@3616.26,3395.94
USB3_OTG0_SSTXN: C39.1 J2.179 | length 2346.7
  TOP w4.5: J2.179@1853.93,2706.42 1853.93,2665.04 1848.84,2659.95 1848.84,2631.16 1950,2530 2108.56,2530 2181,2602.44 2181,2619.02 v1(2171.32,2628.71) ; C39.1@3445,3016.28 3459.25,3002.03 3459.25,2984.55 3467.8,2976 3502.43,2976 3512.5,2986.06 3512.5,3077 3513,3077.5 3513,3077.75 v2(3519.25,3084)
  BOTTOM w4.5: v1(2171.32,2628.71) 2180.5,2637.89 2180.5,2645.5 2195,2660 2207.56,2660 2265.56,2718 2294.57,2718 2311.4,2734.84 2456.06,2879.5 2672.09,2879.5 2982.59,3190 3336,3190 3395,3131 3484,3131 3512,3103 3512,3091.25 v2(3519.25,3084)
USB3_OTG0_SSTXN_: C39.2 D107.4 D107.7 J6.8 | length 689
  TOP w4.5: C39.2@3445,3051.72 3458.5,3065.22 3458.5,3076.06 3451.78,3082.79 3451.78,3113.22 3446.68,3118.32 D107.4@3446.68,3128.78 D107.7@3446.68,3163.22 3446.68,3173.68 3451.78,3178.78 3451.78,3216.78 3472.5,3237.5 3552.06,3237.5 3572.5,3257.94 3572.5,3292.94 3597.5,3317.94 3597.5,3331.94 3635.56,3370 3676.44,3370 3682.44,3364 3708.56,3364 3715.56,3371 3751,3371 3759.5,3362.5 3795.06,3362.5 3805.57,3373 3805.57,3391.43 3801.06,3395.94 J6.8@3773.74,3395.94
USB3_OTG0_SSTXP: C41.1 J2.181 | length 2314.4
  TOP w4.5: J2.181@1834.25,2706.42 1834.25,2665.04 1839.34,2659.95 1839.34,2627.22 1946.06,2520.5 2112.5,2520.5 2190.5,2598.5 2190.5,2620.02 v1(2199.18,2628.71) ; C41.1@3483,3016.28 3468.75,3002.03 3468.75,2988.48 3471.73,2985.5 3498.5,2985.5 3503,2990 3503,3077.25 v2(3496.25,3084)
  BOTTOM w4.5: v1(2199.18,2628.71) 2190,2637.89 2190,2641.56 2198.94,2650.5 2211.5,2650.5 2269.5,2708.5 2298.5,2708.5 2320.9,2730.9 2460,2870 2676.03,2870 2986.53,3180.5 3332.06,3180.5 3391.06,3121.5 3480.06,3121.5 3502.5,3099.06 3502.5,3090.25 v2(3496.25,3084)
USB3_OTG0_SSTXP_: C41.2 D107.5 D107.6 J6.9 | length 721.6
  TOP w4.5: C41.2@3483,3051.72 3468,3066.72 3468,3080 3461.28,3086.72 3461.28,3112.28 3466.37,3117.37 D107.5@3466.37,3128.78 D107.6@3466.37,3163.22 3466.37,3173.63 3461.28,3178.72 3461.28,3212.84 3476.44,3228 3556,3228 3582,3254 3582,3289 3607,3314 3607,3328 3639.5,3360.5 3672.5,3360.5 3678.5,3354.5 3712.5,3354.5 3719.5,3361.5 3747.06,3361.5 3755.56,3353 3799,3353 3815.07,3369.07 3815.07,3405.07 3823.53,3413.53 3841.47,3413.53 3852.48,3402.52 J6.9@3852.48,3395.94
USB3_OTG0_VBUSDET: J2.191 R27.2 R28.2 | length 4131.7
  TOP w5: J2.191@1735.82,2706.42 1735.82,2749.18 1731,2754 1731,2770.59 1736,2775.59 1885.59,2775.59 1974,2864 2283.14,2864 2410,2990.86 2410,3178 v1(2384,3204) ; R28.2@5088,3480.28 R27.2@5125,3480.28 5125.28,3480.28 v1(5104.5,3459.5)
  BOTTOM w5: v1(2384,3204) 2384,3215.78 2406,3237.78 2406,3303.57 2490.43,3388 2525.86,3388 2543.43,3405.57 2562.86,3425 2990,3425 3030,3385 3101,3385 3144,3428 3453,3428 3550,3525 3840,3525 3930,3435 4720,3435 4740,3415 4970,3415 5025,3470 5094,3470 v1(5104.5,3459.5)
USB3_PWREN_H_GPIO4_C4: J2.140 R77.1 | length 3788
  TOP w5: v1(2271.67,1775) 2271.67,1778.33 2251,1799 2251,1841 2313,1903 2313,1981.14 2291.67,2002.47 2291.67,2116.45 2296,2120.78 2296,2240.86 2340,2284.86 2340,2329 2316.53,2352.47 J2.140@2316.53,2383.58 ; v1(3976,1776) 3987,1765 3987,1517 3975,1505 3975,1454 4070,1359 4070,1358.14 4075,1353.14 4075,1322.14 4086,1311.14 4086,1159 4110,1135 4110,1048.72 R77.1@4137,1021.72
  BOTTOM w5: v1(2271.67,1775) 2275,1775 2280,1770 2280,1395 2310,1365 2960,1365 3385,1790 3962,1790 v1(3976,1776)
USB_OTG_PWREN_H_GPIO0_A5: J2.212 R32.1 | length 5821.5
  TOP w5: J2.212@1529.13,2383.58 1529.13,2240.87 1550,2220 1605,2220 1624,2201 1677,2201 1743,2135 1810,2135 1855,2090 v1(1875,2090) ; v1(5146,2151) 5191,2151 5196,2156 5196,2211 5209,2224 v1(5214,2224)
  BOTTOM w5: v1(1875,2090) 1895,2070 1923.08,2070 1945.41,2092.33 1960.59,2092.33 1977.92,2075 2271.57,2075 2343.57,2147 2399.14,2147 2481.14,2065 2841,2065 2925,2149 2925,2365 2895,2395 2895,2748 3040,2893 3063,2893 3085,2915 3538,2915 3609,2844 4008,2844 4049,2885 4295,2885 4330,2920 4500,2920 4630,3050 4708,3050 4743,3085 4967.74,3085 5079,2973.74 5079,2826 5092,2813 5092,2648 5185,2555 5185,2500 5280,2405 5280,2235 5269,2224 v1(5214,2224) ; R32.1@5130,2177.28 5147.6,2159.68 5147.6,2152.6 v1(5146,2151)
USIM_CLK: C185.1 D75.1 R335.2 SIM1.C3 | length 246.6
  BOTTOM w5: SIM1.C3@4730,2718.81 4730,2685 4723,2678 4723,2602.72 C185.1@4708,2587.72 4755.82,2587.72 D75.1@4757,2588.9 4764.1,2588.9 4797.72,2555.28 R335.2@4800,2555.28
USIM_CLK_: J26.12 R335.1 | length 328.5
  TOP w5: J26.12@4831.3,2383.6 4831.3,2415.7 4811,2436 4811,2572 4824,2585 4824,2624 v1(4835,2635)
  BOTTOM w5: R335.1@4800,2590.72 4835,2625.72 v1(4835,2635)
USIM_DATA: C188.1 D73.1 R331.1 R334.2 SIM1.C7 | length 1403.5
  TOP w5: v1(4735,3561) 4740,3556 4740,3222 4766,3196 4780,3196 4824,3152 4824,2978 4804,2958 4804,2869 v1(4795,2860)
  BOTTOM w5: SIM1.C7@4730,3623.19 4730,3566 v1(4735,3561) ; R334.2@4790.28,2436 C188.1@4749.72,2436 4744.72,2441 R331.1@4744.72,2474 4783.1,2474 D73.1@4787.1,2478 4787.1,2482.1 4835,2530 4835,2589.14 4881,2635.14 4881,2717 4795,2803 v1(4795,2860)
USIM_DATA_: J26.10 R334.1 | length 86.7
  TOP w5: v1(4858,2436) 4862.8,2431.2 J26.10@4862.8,2383.6
  BOTTOM w5: R334.1@4825.72,2436 v1(4858,2436)
USIM_RST: C184.1 D72.1 R332.2 R336.2 SIM1.C2 | length 298
  BOTTOM w5: R332.2@4543,2551.28 4578.44,2586.72 C184.1@4582,2586.72 4601.33,2586.72 4602.33,2587.72 4603.12,2587.72 4604.3,2588.9 D72.1@4625,2588.9 ; SIM1.C2@4630,2718.81 4630,2690 4640,2680 4640,2623 4625,2608 D72.1@4625,2588.9 ; R336.2@4670,2552.28 4633.38,2588.9 D72.1@4625,2588.9
USIM_RST_: J26.14 R336.1 | length 344.4
  TOP w5: v1(4700,2631) 4700,2600 4760,2540 4760,2455 4799.8,2415.2 J26.14@4799.8,2383.6
  BOTTOM w5: R336.1@4670,2587.72 4670,2601 v1(4700,2631)
USIM_VDD: C183.1 C186.1 D74.1 R331.2 R332.1 R333.2 SIM1.C1 | length 895.8
  TOP w20: v1(4550.8,2623.8) 4552,2622.61 4552,2604 4680,2476 v1(4680,2474) 4682,2474 4708.17,2447.83 4709.03,2447.83 4724.15,2432.7 4724.15,2431.85 4730,2426 4730,2335 4828.54,2236.46 R333.2@4875,2236.46
  BOTTOM w20: C183.1@4410,2587.72 C186.1@4450,2587.72 4488.82,2587.72 D74.1@4490,2588.9 4505,2603.9 ; SIM1.C1@4530,2718.81 4530,2666.81 4505,2641.81 4505,2603.9 ; R332.1@4543,2586.72 4543,2616 v1@4547.06,2620.06 ; v1(4550.8,2623.8) v1@4547.06,2620.06 ; v1(4680,2474) R331.2@4709.28,2474 ; 4505,2603.9 4521.16,2620.06 v1@4547.06,2620.06
VBAT_RTC: D70.A J25.1 | length 2970
  TOP w15: D70.A@3255,1584.57 3255,1555 3238,1538 3238,1272 v1(3355,1155)
  TOP w20: v1(1310.39,499.61) J25.1@1310.39,550 ; v1(3011,630) 3011,673 3095,757 v1(3095,900)
  BOTTOM w20: v1(1310.39,499.61) 1320,490 1640,490 1750,380 v1(3025,380) ; v1(3095,900) 3350,1155 v1(3355,1155)
VBAT_WL_1T1R: C118.2 C119.2 C125.2 Q10.3 R202.2 U18.9
  other v1: 4915,1150 4900,1170 4930,1170 5094,1625 5094,1650 5094,1675
VBUSM: R74.1 U8.35 | length 225.7
  TOP w10: R74.1@4232.72,2077 4363,2077 4370,2070 4395,2070 4416.4,2048.6 U8.35@4416.4,2018.3
VCC1V5_DVP: C100.2 C106.2 C107.2 C108.1 C254.2 J19.3 J20.3 R175.2 U16.5 | length 1835.7
  TOP w10: J20.3@2101.3,632.01 2101.3,668.58 C100.2@2150,717.28
  TOP w12: J19.3@2852.01,632.01 2852.01,672.01 v1(2915,735)
  TOP w15: C100.2@2150,717.28 2156,711.28 v1(2156,691) ; R175.2@2690,1072.28 C108.1@2730,1072.28 2737.28,1072.28 2772.72,1107.72 C107.2@2780,1107.72 ; v1(2915,735) C254.2@2915,757.28
  TOP w20: U16.5@2762.4,1171.85 2762.4,1152.6 2780,1135 C107.2@2780,1107.72 2824.84,1107.72 C106.2@2825,1107.56 2837.44,1107.56 2865,1080 2865,1023 2889,999 2952,999 3015,936 3015,840 v1(2985,810)
  BOTTOM w20: v1(2156,691) 2157,692 2434,692 2448,706 2750,706 2768,688 2868,688 v1(2915,735) 2915,738 2985,808 v1(2985,810)
VCC1V8_DVP: C102.2 C103.2 C104.2 C255.2 J19.4 J20.4 Q16.1 Q17.1 R156.2 R161.2 R162.2 R166.2 R172.2 U15.5 | length 2703.1
  TOP w10: Q16.1@1913.32,899.5 1914,900.19 1914,925 1921.07,932.07 1994,932.07 ; R161.2@1985,835.72 1979,841.72 1979,882 1994.32,897.32 Q17.1@1994.32,899.5 1994,899.82 1994,932.07 ; v1(2069,925) 2057,925 2049.93,932.07 1994,932.07 ; J20.4@2081.61,632.01 2081.61,680.89 v1(2092.36,691.64) ; R162.2@2120.72,899 2120.72,903 v1(2143.86,926.14)
  TOP w12: J19.4@2832.32,632.01 2832.32,677.32 2875,720 v1(2875,735)
  TOP w15: v1(2092.36,691.64) 2110,709.28 C104.2@2110,717.28 ; R166.2@2140,835.72 2210.72,835.72 v1(2230,855) 2230,911 2194.23,946.77 2194.1,946.77 2191.66,949.21 2172.34,949.21 2149.27,926.14 v1(2143.86,926.14) ; v1(2875,735) C255.2@2875,757.28
  TOP w20: v1(2230,640) 2225,645 2225,780 2290,845 v1(2290,855) 2290.5,854.5 2312.5,854.5 2342,884 2342,901 2416,975 2590,975 v1(2610,995) 2610,1017 2624,1031 2624,1091 2607.44,1107.56 C102.2@2590,1107.56 2546.16,1107.56 C103.2@2546,1107.72 ; R172.2@2490,1072.28 2502.28,1072.28 2520,1090 2520,1095 2532.72,1107.72 C103.2@2546,1107.72 ; U15.5@2560.98,1165.07 2560.98,1140.98 2546,1126 C103.2@2546,1107.72 ; v1(2950,915) 2960,905 R156.2@2960,887.72
  BOTTOM w15: v1(2069,925) 2075,919 2136.72,919 v1(2143.86,926.14) ; v1(2230,855) v1(2290,855)
  BOTTOM w20: v1(2092.36,691.64) 2104.36,691.64 2156,640 v1(2230,640) ; v1(2610,995) 2635,970 2635,915 2670,880 2805,880 2850,835 ; v1(2875,735) 2850,760 2850,835 ; v1(2950,915) 2915,880 2895,880 2850,835
VCC2V8_DVP: C98.2 C110.2 C111.2 C253.2 J19.1 J19.2 J20.1 J20.2 R177.2 U17.5 | length 1441.9
  TOP w15: R177.2@2941,1069.28 2946.28,1069.28 2979.72,1102.72 C111.2@2985,1102.72
  TOP w20: C253.2@2955,757.28 2979,757.28 2980,758.28 v1(2980,759.28) 3040,819.28 3040,1000 3065,1025 3065,1075 3037.44,1102.56 C110.2@3030,1102.56 2985.16,1102.56 C111.2@2985,1102.72 2985,1130 2980.12,1134.88 U17.5@2980.12,1170.79
  BOTTOM w20: v1(2195,666) 2442,666 2468,640 2734,640 2757,663 2883.72,663 v1(2980,759.28)
VCC3V3_PHY0: C148.2 C149.2 C150.2 C151.2 C152.2 R211.2 R226.2 R230.2 R258.2 U19.11 U19.29 U19.40 | length 1326.4
  TOP w8: C151.2@1705,1682.72 1705,1689.88 1715.12,1700 U19.29@1715.12,1777.48
  TOP w10: U19.40@1752.52,1940.87 1780.87,1940.87 1822.5,1982.5 1849.78,1982.5 C149.2@1862.28,1995
  TOP w15: C148.2@1396.72,1999 1397.72,2000 R258.2@1397.72,2035 1401.72,2039 1445.39,2039 1460,2024.39 1460,2018 1475.72,2002.28 1477.72,2002.28 C150.2@1477.72,1995 ; C151.2@1705,1682.72 C151.2@1712,1682.72 C152.2@1745,1682.72 ; v1(1740,1705) 1745,1700 C152.2@1745,1682.72 ; v1(1775,1655) 1775,1665 1757.28,1682.72 C152.2@1745,1682.72 ; v1(1810,1732) 1815.5,1726.5 1855.72,1726.5 1872.72,1743.5 R226.2@1872.72,1750 ; C149.2@1862.28,1995 1862.28,2032.28 1880,2050 R211.2@1892.28,2050 v1(1892.28,2027.28) ; v1(2022,1724) 2030.28,1732.28 R230.2@2045,1732.28
  BOTTOM w15: v1(1775,1655) 1810,1690 v1(1810,1732) ; v1(1892.28,2027.28) 1915,2050 2070,2050 2085,2035 2085,1890 2070,1875 2070,1810 2047,1787 2047,1749 v1(2022,1724)
  other v1: 1500,1955 1500,1977
VCC3V3_PHY1: C172.2 C173.2 C174.2 C175.2 C176.1 R274.2 R278.2 R306.2 U20.11 U20.29 U20.40 | length 1753.9
  TOP w10: v1(2505,1975) 2544.13,1935.87 U20.11@2562.48,1935.87 ; v1(2686,1705) 2686,1718 2710.12,1742.12 U20.29@2710.12,1772.48 ; U20.40@2747.52,1935.87 2765.87,1935.87 2789,1959 2804,1959 2845,2000 2845,2014
  TOP w15: C174.2@2480.72,1992 2488,1992 v1(2505,1975) ; v1(2794.5,1978.5) 2830,2014 2845,2014 ; R278.2@2972.72,1733 R274.2@2972.72,1695 2972.72,1629.28 2986,1616 R306.2@2986,1598.72
  TOP w20: v1(2686,1705) 2708,1705 2728,1685 C175.2@2728,1667.72 C176.1@2765,1667.72 v1(2765,1689) ; 2845,2014 2845,2030.28 C173.2@2852,2037.28 ; v1(2930,1660) 2930,1612.72 C172.2@2945,1597.72 2946,1598.72 R306.2@2986,1598.72
  BOTTOM w20: v1(2686,1705) 2540,1705 2430,1815 2430,1910 2495,1975 v1(2505,1975) 2508.5,1978.5 v1(2794.5,1978.5) ; v1(2765,1689) 2794,1660 v1(2930,1660)
VCC3V3_SD: C31.2 D2.2 J2.210 J3.4 | length 4522.4
  TOP w10: 1548.81,2336.19 J2.210@1548.81,2383.58
  TOP w15: 1548.81,2336.19 1548.81,2250 1563.81,2235 1614,2235 1633,2216 1684,2216 1750,2150 1820,2150 1856,2114 1884,2114 v1(1906,2092) ; J3.4@4429.92,3262.13 4429.92,3229.92 4365,3165 D2.2@4365,3143.9 4413.66,3143.9 C31.2@4415,3142.56 4437.56,3120 v1(4445,3120)
  BOTTOM w15: v1(1906,2092) 1923.87,2092 1939.19,2107.33 1966.81,2107.33 1984.13,2090 2265.36,2090 2337.36,2162.01 2349.78,2162.01 2358.06,2162 2405.36,2162 2487.36,2080 2832,2080 2909,2157 2909,2356 2880,2385 2880,2755 3033,2908 3056,2908 3078,2930 3545,2930 3616,2859 4001,2859 4042,2900 4122,2900 4152,2930 4267,2930 4272,2935 4490,2935 4540,2985 4540,3010 4510,3040 4510,3090 4480,3120 v1(4445,3120)
VCC5V0_M: C26.2 C27.2 C28.2 C29.2 J2.253 J2.255 J2.257 J2.259 R17.2
  other v1: 1147,2770 1172,2770 1195,2770 1220,2770 1245,2770 1148,2800 1205,2800
VCC5V0_USB1: C42.1 D19.2 J7.1 U7.1 | length 50.4
  TOP w40: J7.1@5084.29,405 5084.29,440.29 5095,451
  other v1: 5196,820 5196,845 4980,1040 5010,1040
VCC5V0_USB2: C46.1 D21.2 J8.1 U9.1 | length 61.2
  TOP w25: 4619.97,405 J8.1@4650.59,405 4650.59,435.62
VCC5V0_USB3: C52.1 D24.2 J9.1 U10.1 | length 61.2
  TOP w25: 4186.27,405 J9.1@4216.89,405 4216.89,435.62
VCC5V0_USB_HOST1: C38.1 D16.1 J6.10 U6.1 | length 145
  TOP w25: 3832.8,3358.02 J6.10@3832.8,3329.02 3861.8,3329.02
  BOTTOM w25: 3803.8,3329.02 J6.10@3832.8,3329.02 ; 3832.8,3358.02 J6.10@3832.8,3329.02 ; 3861.8,3329.02 J6.10@3832.8,3329.02
  other v1: 3879,3189 3898,3204
VCC5V0_USB_HOST2: C36.1 D15.1 J6.1 U5.1 | length 66
  TOP w40: J6.1@3832.8,3455 3896,3455 3898,3453
VCC5V0_USB_OTG0: C32.2 C34.1 D7.2 J5.A4 J5.A9 J5.B4 J5.B9 R27.1 U4.1 | length 46.5
  TOP w8: R27.1@5125,3515.72 5169.82,3515.72 D7.2@5171,3516.9
  other v1: 5006,2490 4981,2494 5339,3068 5317,3084 5440,3545 5465,3545 5165,3550 5188,3550
VCC5V_HDMI_TX: C85.2 D43.C J14.18 | length 434.7
  TOP w12: J14.18@2939.65,3465 2939.65,3519.65 2950,3530 2975,3530 2990,3515 2990,3461 3043,3408 3095,3408 3134,3369 C85.2@3134,3355.72 3160.45,3382.17 3162.04,3382.17 3168.96,3389.09 D43.C@3190,3389.09
VCC5V_SPK: C249.2 C250.2 C251.2 C252.2 R86.2 U11.4 U11.13 | length 694
  TOP w20: R86.2@4530,2959.37 4598,3027.37 C250.2@4598,3027.56 C251.2@4655,3027.56 4667.56,3015 U11.4@4735,3015 4780,3015 v1(4795,3000) ; U11.13@4975,3015 5010,3015 5020,3025 5062.44,3025 C249.2@5072.44,3015 C252.2@5072.44,2960 5054.44,2942 v1@5024.38,2942
  BOTTOM w20: v1(4795,3000) 4968,3000
  other v1: 5029,2926 5029,2950 4775,3000
VCC5V_SYS: C8.2 C9.2 C10.2 C11.2 D42.A D43.A L2.2 Q5.1 R4.2 R7.2 R17.1 | length 1571.6
  TOP w10: Q5.1@2956.32,3195.5 2999,3238.19 v1(2999,3242)
  TOP w15: 2442.49,3597.51 2547.49,3597.51 2565,3580 3105,3580 3120,3565 3120,3507 3185,3442 3219,3442 3240,3421 3240,3351 3190,3301 D43.A@3190,3274.91 D42.A@3190,3240.09 ; C8.2@3122.72,2983 R4.2@3122.72,3019 3160,3019 3171,3030 v1(3171,3044) ; v1(3171,3243) 3187.09,3243 D42.A@3190,3240.09 ; R7.2@3255,3203.28 3255,3201.28 3241.72,3201.28 3213.91,3229.09 D42.A@3201,3229.09 D42.A@3190,3240.09
  BOTTOM w8: v1(2999,3242) 3039,3242 3061,3264 3159,3264 3171,3252 v1(3171,3243)
  other v1: 1080.93,2831.55 1057.62,2844.48 1075.62,2864.14 1047,2868 2586,2904 2615,2905 2643,2905 2667,2905 2615,2930 2643,2930 2670,2930 2449.35,3273 2476,3273 2435,3291 2462,3292 2476.23,3314.54 1265,3648 1210.85,3651.15 1240,3651 1255,3669 1192,3670 1228.52,3671.11
VCC12V_DCIN: C256.2 C257.2 F2.1 J1.4 J17.1 J18.5 J18.6 J29.1 J30.5 J30.6 J32.3 J32.4 | length 1340.7
  TOP w25: 367.6,3488.4 J1.4@406.1,3488.4 ; 406.1,3422.34 J1.4@406.1,3488.4 ; 406.1,3554.46 J1.4@406.1,3488.4 ; 426.46,875.79 J30.6@457.09,875.79 ; 426.46,954.53 J30.5@457.09,954.53 457.09,923.9 ; 444.27,3594 J32.4@474.89,3594 ; 444.59,3488.4 J1.4@406.1,3488.4 ; 457.09,845.16 J30.6@457.09,875.79 ; 457.09,906.41 J30.6@457.09,875.79 ; 474.89,3563.38 J32.4@474.89,3594 ; 474.89,3624.62 J32.4@474.89,3594 ; 487.71,875.79 J30.6@457.09,875.79 ; 505.51,3594 J32.4@474.89,3594 ; 523.01,3594 J32.3@553.63,3594 ; 553.63,3624.62 J32.3@553.63,3594 ; 577.41,880 J29.1@610,880 ; 584.25,3594 J32.3@553.63,3594 ; 610,847.41 J29.1@610,880 ; 642.59,880 J29.1@610,880 ; 922.49,405 J18.5@953.11,405 ; 953.11,374.38 J18.5@953.11,405 ; 953.11,435.62 J18.5@953.11,405 ; 983.73,405 J18.5@953.11,405 ; 1001.23,405 J18.6@1031.85,405 ; 1031.85,374.38 J18.6@1031.85,405 ; 1031.85,435.62 J18.6@1031.85,405 ; 1062.47,405 J18.6@1031.85,405 ; 1065,522.41 J17.1@1065,555 ; 1065,587.59 J17.1@1065,555 ; 1097.59,555 J17.1@1065,555
  TOP w80: 930,3128 932,3126 F2.1@932,2970
  BOTTOM w20: J1.4@406.1,3488.4 406.1,3525.21 J32.4@474.89,3594
VCC_1V8: J2.237 Q19.1 R30.2 R154.2 R155.2 R200.1 R250.1 R298.1 R398.1 R399.1 R408.1 R413.1 | length 12216.9
  TOP w10: R399.1@5273,1512.28 5286.28,1512.28 5304,1530 5304,1624.68
  TOP w15: 1283.07,2656.07 J2.237@1283.07,2706.42 ; R298.1@2766.72,1461 2783,1461 2835.5,1408.5 2835.5,1225 ; Q19.1@5273.5,1624.68 5304,1624.68 5351.69,1624.68 v1(5361,1634)
  TOP w20: v1(860.35,2097.53) 860.35,2088.82 861.5,2087.67 861.5,1762.5 905,1719 905,1636 1022,1519 1189.13,1519 1234.07,1474.06 ; R408.1@1168,1407.28 1189,1407.28 1209,1427.28 1209,1448.98 1234.07,1474.06 ; 1247.3,1460.83 1234.07,1474.06 ; 1247.34,1460.83 1255.17,1453 1269.35,1453 v1(1270.18,1452.17) ; 1283.07,2656.07 1283.07,2564.93 v1(1290,2558) ; R250.1@1722.72,1470 1722.72,1459 v1(1738.86,1442.86) ; v1(2007,1093) 2009,1091 2009,1077 2042,1044 2122,1044 2161.49,1004.5 2184.49,1004.5 2225,964 v1(2225,951) ; v1(2431,1190) 2431,1202 2454,1225 2835.5,1225 2998,1225 3014.01,1208.99 3014.01,1165 3034.01,1145 3055,1145 3095,1105 3095,1010 3070,985 3070,972 ; R154.2@2767,967.72 2779.19,967.72 2783.3,971.83 2804.7,971.83 2808.81,967.72 R155.2@2821,967.72 2937.28,967.72 v1(2980,925) ; v1(3070,925) 3070,972 ; v1(3210,972) 3070,972 ; R413.1@3845,852.72 3845,879 v1(3846,880) ; v1(4093.35,1332.72) R200.1@4120,1332.72 ; v1(4107,563) 4107,381 4134,354 5334,354 5539,559 5539,717 5486,770 v1(5473,770) ; v1(4795,2195) 4900,2090 5068,2090 5102,2124 5211,2124 5245,2090 5326,2090 5371,2045 v1(5390,2045) ; R398.1@5312.72,1760 5312.72,1772.72 v1(5325,1785)
  BOTTOM w19: 1866,1116 1867.44,1116 1867.51,1115.93 1888.49,1115.93 1888.56,1116 1900.27,1116
  BOTTOM w20: v1(860.35,2097.53) 860.35,2119.35 861.5,2120.5 861.5,2126.03 875,2139.53 875,2259 979,2363 979,2431 999,2451 1064,2451 1171,2558 v1(1290,2558) ; v1(1270.18,1452.17) 1271,1452.17 1272.83,1454 1291,1454 1351,1394 1353.25,1394 1354.75,1392.5 1592.75,1392.5 1629.42,1429.17 1725.17,1429.17 v1(1738.86,1442.86) 1751.72,1430 1814,1430 1846,1398 1846,1314 1837,1305 1837,1145 1866,1116 ; 1900.27,1116 1984,1116 v1(2007,1093) ; v1(2225,951) 2255,951 2261.5,957.5 2277.61,973.61 2299,995 2299,1059 2430,1190 v1(2431,1190) ; v1(2980,925) v1(3070,925) ; v1(3702.07,546.85) 3697,551.91 3697,693.88 3748.12,745 3826,745 3846,765 3846,840 ; v1(3846,880) 3846,840 ; v1(4093.35,1332.72) 4049.72,1332.72 3974,1257 3974,1213 ; v1(4107,563) 4133,589 4133,990 4039.5,1083.5 4039.5,1166.5 3993,1213 3974,1213 ; v1(4795,2195) 4795,2263 4832,2300 4881.28,2300 R30.2@4882.28,2299 ; v1(5390,2045) 5390,1850 v1(5325,1785) 5361,1749 v1(5361,1634) 5361,916 5384,893 5384,836 5438,782 5461,782 v1(5473,770) ; 3846,840 3838,848 3791,848 3769,870 3769,989 3753,1005 3580,1005 3552.64,1032.36 3552.64,1085.61 3638.17,1171.14 3638.17,1171.7 3653.3,1186.83 3653.86,1186.83 3659.03,1192 3852,1192 3873,1213 3974,1213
